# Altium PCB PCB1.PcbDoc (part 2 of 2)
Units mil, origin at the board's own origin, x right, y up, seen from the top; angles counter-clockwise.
Board outline 3935 x 3935 mil, 2 copper layers (Top Layer, Bottom Layer); 151 components, 133 nets, 573 pads, 224 vias.
Unrouted connection lines stored in the file: 1.
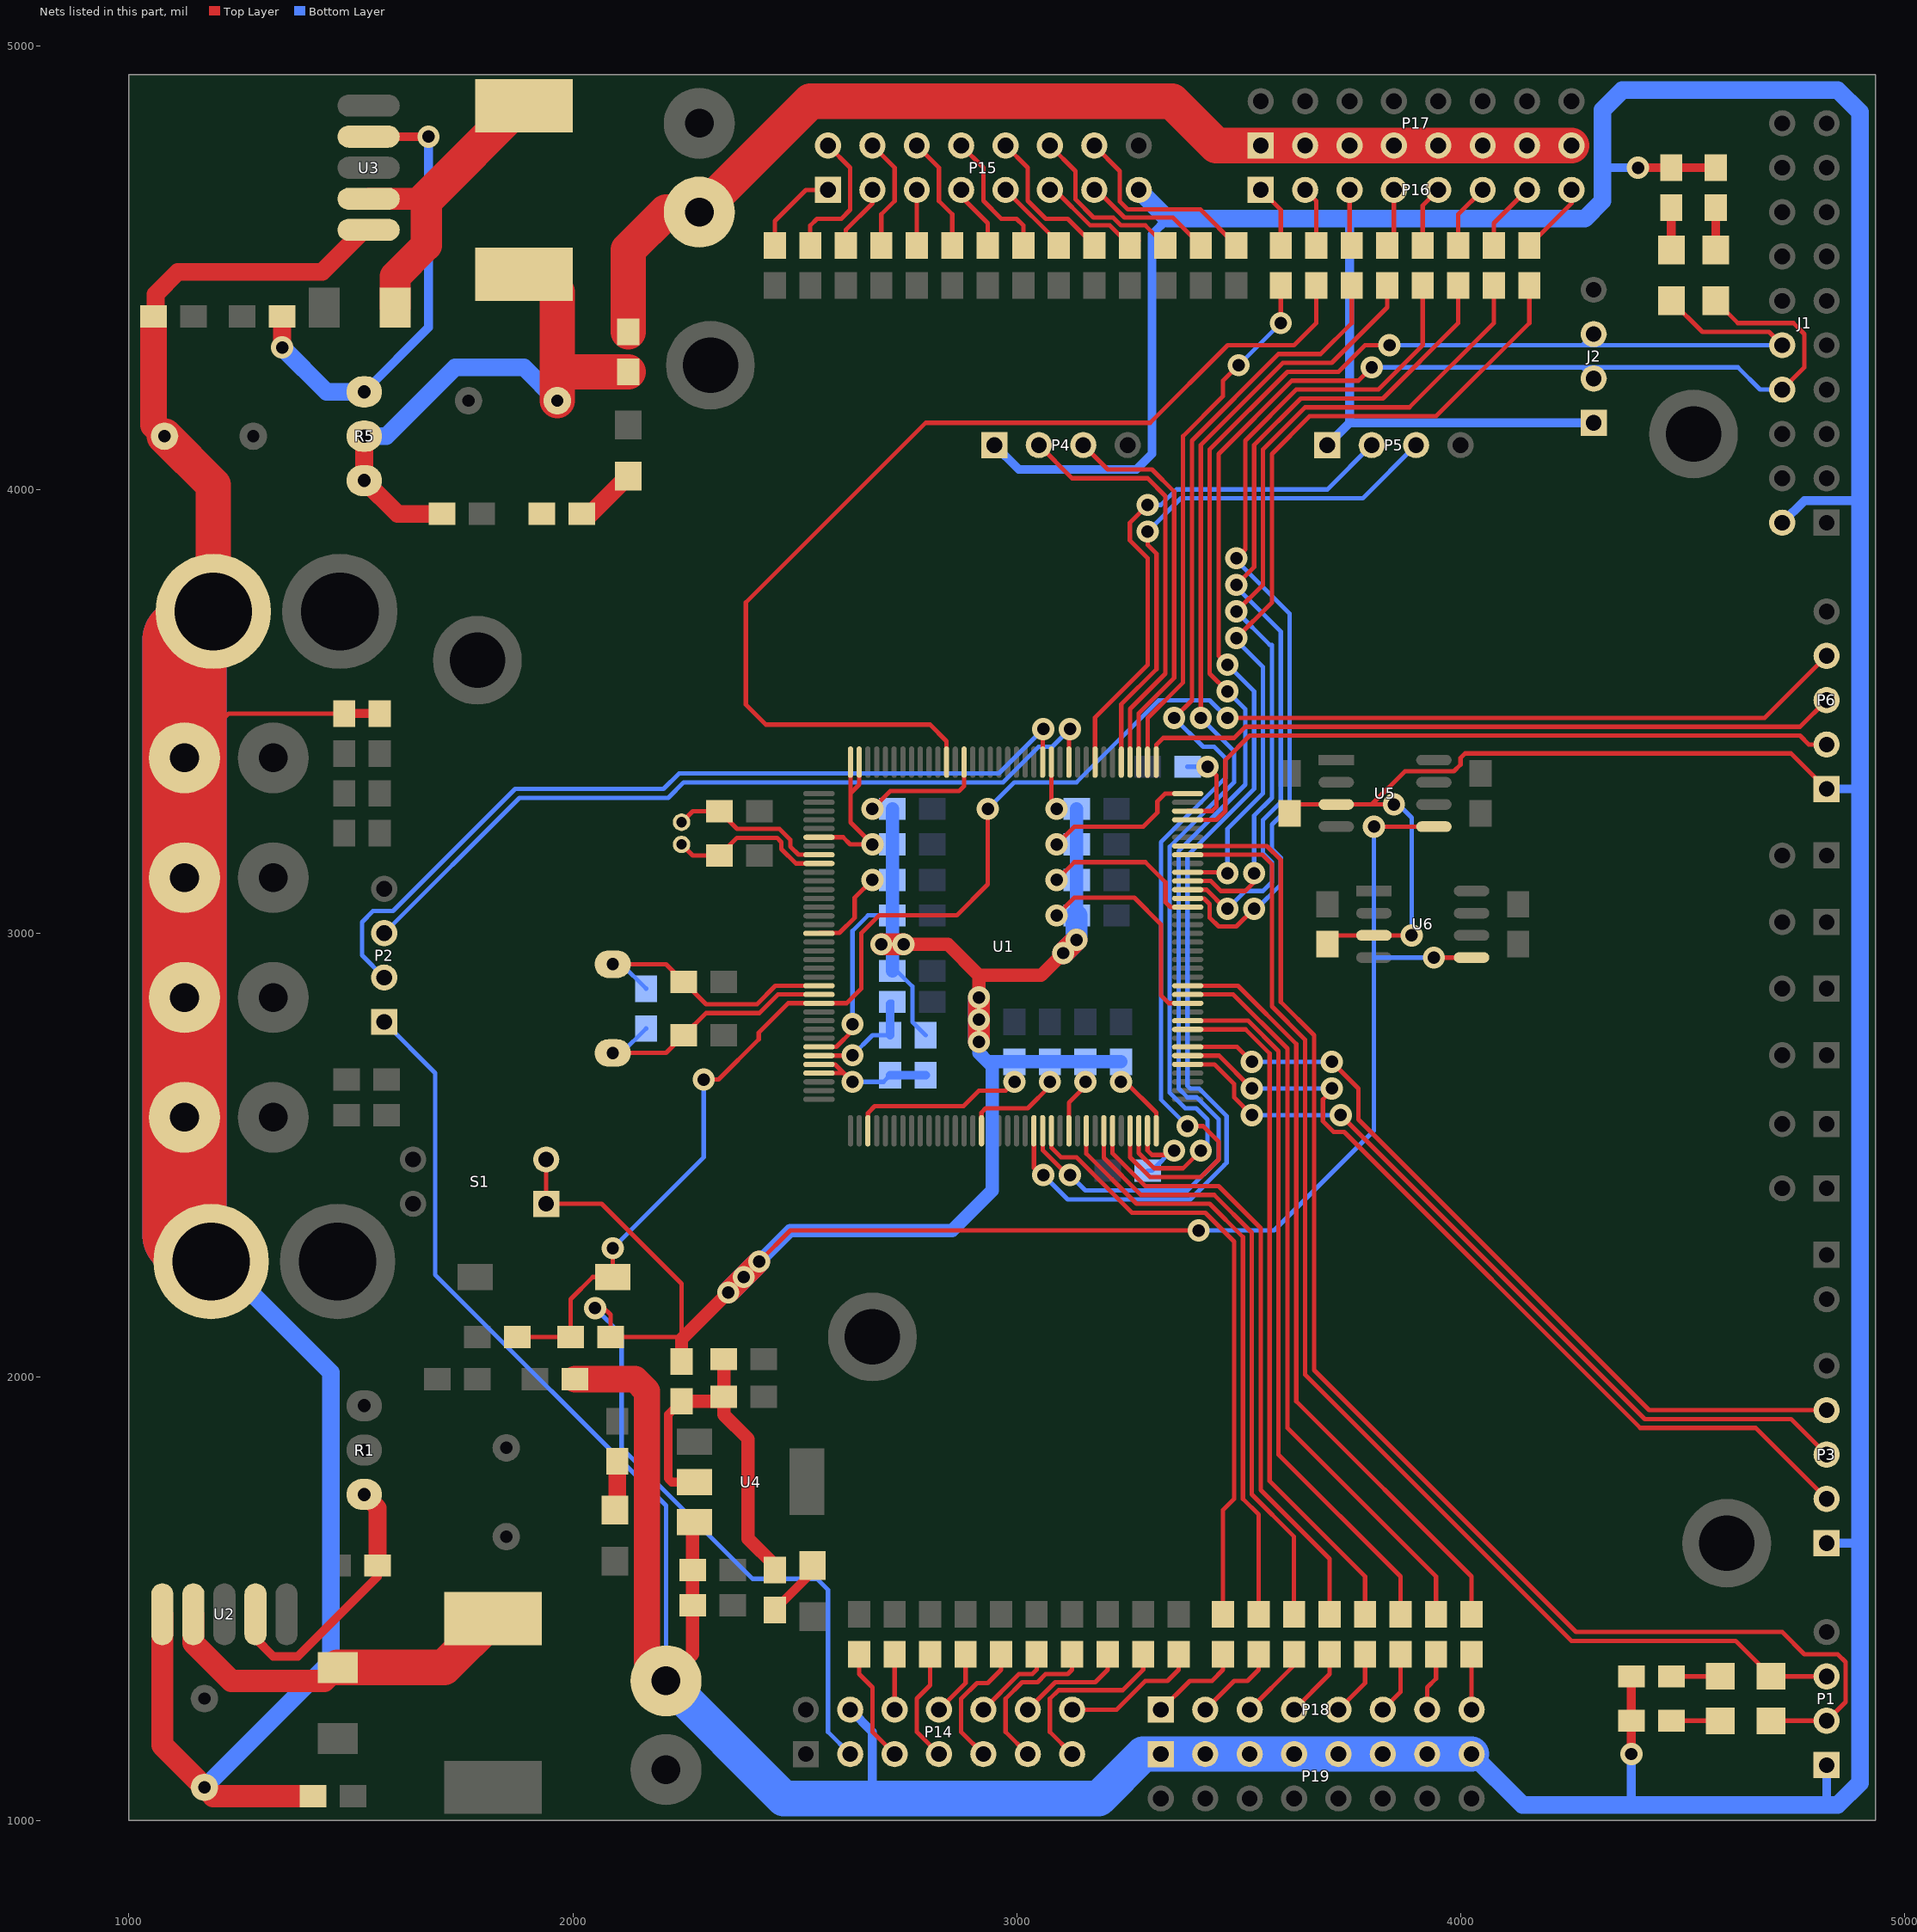
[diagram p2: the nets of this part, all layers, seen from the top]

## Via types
v1: diameter 50, hole 28, Top Layer to Bottom Layer, tented both sides, 126 vias
v2: diameter 30, hole 20, Top Layer to Bottom Layer, tented both sides, 98 vias

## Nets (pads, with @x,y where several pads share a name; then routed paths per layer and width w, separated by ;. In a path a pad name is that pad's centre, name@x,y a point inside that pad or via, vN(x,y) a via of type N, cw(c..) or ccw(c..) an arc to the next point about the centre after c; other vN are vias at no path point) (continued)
NetC7_1: C7.1 C8.1 L2.2 R5.2 R5.3 R7.1 R8.1 | length 1297.9
  Top Layer w40: R5.2@1530,4120 R5.3@1530,4020 1605,3945 C7.1@1705,3945
  Top Layer w80: L2.2@1925,4485 1965,4445 1965,4265 ; C8.1@1965,4200 1965,4265 ; R8.1@2125,4265 1965,4265
  Bottom Layer w40: R5.2@1530,4120 1580,4120 1735,4275 1890,4275 C8.1@1965,4200
NetC11_1: C11.1 C12.2 R9.1 R65.2 U4.2 | length 870.5
  Top Layer w10: C12.2@2330,1945 C12.2@2340,1955
  Top Layer w20: R9.1@2245,1945 2215,1915 2215,1771 2223,1763 U4.2@2274,1763 ; R65.2@2455,1565 R65.2@2455,1575
  Top Layer w30: R9.1@2245,1945 C12.2@2330,1945 ; C11.1@2340,2040 C12.2@2340,1955 2340,1915 2395,1860 2395,1635 R65.2@2455,1575
NetC19_1: C19.1 R20.2 U1.23 Y1.1 | length 616.9
  Top Layer w10: Y1.1@2090,2930 2210,2930 C19.1@2250,2890 2300,2840 2415,2840 2456.42,2881.42 U1.23@2554.65,2881.42
  Bottom Layer w10: Y1.1@2090,2930 2110,2930 R20.2@2165,2875
NetC20_1: C20.1 R20.1 U1.24 Y1.2 | length 617
  Top Layer w10: Y1.2@2090,2730 2210,2730 C20.1@2250,2770 2300,2820 2420.46,2820 2462.19,2861.73 U1.24@2554.65,2861.73
  Bottom Layer w10: Y1.2@2090,2730 2110,2730 R20.1@2165,2785
NetC21_2: C21.2 U1.106 | length 212
  Top Layer w10: U1.106@3385.35,3275.12 3440.12,3275.12 3450,3285 3450,3355 v1(3430,3375)
  Bottom Layer w10: C21.2@3385,3375 v1(3430,3375)
NetC22_2: C22.2 U1.71 | length 198.7
  Top Layer w10: U1.71@3294.8,2554.65 3294.8,2510.2 3305,2500 3345,2500 v1(3355,2510)
  Bottom Layer w10: C22.2@3295,2465 3305,2465 3355,2515 v1(3355,2510)
NetC23_2: C23.2 U1.8 Y2.2 | length 369.8
  Top Layer w10: Y2.2@2245,3250 2270,3275 C23.2@2330,3275 2370,3235 2465.46,3235 2490,3210.46 2490,3195 2508.31,3176.69 U1.8@2554.65,3176.69
NetC24_2: C24.2 U1.9 Y2.1 | length 369.6
  Top Layer w10: Y2.1@2245,3200 2270,3175 C24.2@2330,3175 2370,3215 2460,3215 2470,3205 2470,3189.54 2502.54,3157.01 U1.9@2554.65,3157.01
NetD1_2: D1.2 L1.1 U2.2 | length 833
  Top Layer w50: U2.2@1145,1465 1145,1400.41 1230.41,1315 1440,1315 D1.2@1470,1345
  Top Layer w80: D1.2@1470,1345 1710,1345 L1.1@1820,1455
NetD2_1: D2.1 R3.2 | length 112.1
  Top Layer w10: D2.1@2095,1700 D2.1@2100,1705
  Top Layer w40: D2.1@2100,1705 R3.2@2100,1810
NetD3_2: D3.2 L2.1 U3.2 | length 749.5
  Top Layer w50: U3.2@1540,4655 1670,4655
  Top Layer w70: D3.2@1600,4410 1600,4480 1670,4550 1670,4655
  Top Layer w80: 1670,4655 1882.5,4867.5 L2.1@1927.5,4867.5
NetD4_1: D4.1 R7.2 | length 140.2
  Top Layer w10: R7.2@2020,3945 R7.2@2040,3945
  Top Layer w40: R7.2@2040,3945 D4.1@2125,4030
NetD5_1: D5.1 R65.1 | length 135.2
  Top Layer w10: D5.1@2540,1560 D5.1@2540,1575
  Top Layer w20: R65.1@2455,1475 D5.1@2540,1560
NetD6_1: D6.1 R66.1 | length 110
  Top Layer w10: R66.1@4475,1225 D6.1@4585,1225
NetD7_1: D7.1 R67.1 | length 110
  Top Layer w10: R67.1@4475,1325 D7.1@4585,1325
NetD8_1: D8.1 R68.1 | length 95
  Top Layer w20: D8.1@4575,4540 R68.1@4575,4635
NetD9_1: D9.1 R69.1 | length 95
  Top Layer w20: D9.1@4475,4540 R69.1@4475,4635
NetP14_5: P14.5 R25.2 | length 258.1
  Top Layer w10: R25.2@2645,1375 2645,1330 2675,1300 2675,1200 P14.5@2725,1150
NetP14_6: P14.6 R26.1 | length 125
  Top Layer w10: P14.6@2725,1250 R26.1@2725,1375
NetP14_7: P14.7 R27.2 | length 258.1
  Top Layer w10: R27.2@2805,1375 2805,1305 2775,1275 2775,1200 P14.7@2825,1150
NetP14_8: P14.8 R28.1 | length 149.9
  Top Layer w10: P14.8@2825,1250 2885,1310 R28.1@2885,1375
NetP14_9: P14.9 R29.2 | length 297.4
  Top Layer w10: P14.9@2925,1150 2875,1200 2875,1274.54 2910.46,1310 2935,1310 2965,1340 R29.2@2965,1375
NetP14_10: P14.10 R30.1 | length 192.3
  Top Layer w10: P14.10@2925,1250 3005,1330 3035,1330 3045,1340 R30.1@3045,1375
NetP14_11: P14.11 R31.2 | length 357.4
  Top Layer w10: P14.11@3025,1150 2975,1200 2975,1274.54 3012.46,1312 3047,1312 3065,1330 3115,1330 3125,1340 R31.2@3125,1375
NetP14_12: P14.12 R32.1 | length 252.3
  Top Layer w10: P14.12@3025,1250 3087,1312 3177,1312 3205,1340 R32.1@3205,1375
NetP14_13: P14.13 R33.2 | length 417.4
  Top Layer w10: P14.13@3125,1150 3075,1200 3075,1274.54 3094.46,1294 3239,1294 3285,1340 R33.2@3285,1375
NetP14_14: P14.14 R34.1 | length 312.3
  Top Layer w10: P14.14@3125,1250 3225,1250 3290,1315 3340,1315 3365,1340 R34.1@3365,1375
NetP15_1: P15.1 R35.2 | length 208.1
  Top Layer w10: R35.2@2465,4550 2455,4560 2455,4605 2525,4675 P15.1@2575,4675
NetP15_2: P15.2 R36.1 | length 315.2
  Top Layer w10: R36.1@2535,4550 2535,4595 2550,4610 2605,4610 2625,4630 2625,4725 P15.2@2575,4775
NetP15_3: P15.3 R37.2 | length 149.9
  Top Layer w10: R37.2@2615,4550 2615,4585 2675,4645 P15.3@2675,4675
NetP15_4: P15.4 R38.1 | length 258.1
  Top Layer w10: P15.4@2675,4775 2725,4725 2725,4650 2695,4620 R38.1@2695,4550
NetP15_5: P15.5 R39.2 | length 125
  Top Layer w10: R39.2@2775,4550 P15.5@2775,4675
NetP15_6: P15.6 R40.1 | length 258.1
  Top Layer w10: P15.6@2775,4775 2825,4725 2825,4650 2855,4620 R40.1@2855,4550
NetP15_7: P15.7 R41.2 | length 149.9
  Top Layer w10: P15.7@2875,4675 2875,4660 2935,4600 R41.2@2935,4550
NetP15_8: P15.8 R42.1 | length 303.2
  Top Layer w10: P15.8@2875,4775 2925,4725 2925,4650.46 2965.46,4610 3000,4610 3015,4595 R42.1@3015,4550
NetP15_9: P15.9 R43.2 | length 174.7
  Top Layer w10: P15.9@2975,4675 3095,4555 R43.2@3095,4550
NetP15_10: P15.10 R44.1 | length 336.9
  Top Layer w10: P15.10@2975,4775 3025,4725 3025,4650.46 3065.46,4610 3115,4610 R44.1@3175,4550
NetP15_11: P15.11 R45.2 | length 245.9
  Top Layer w10: P15.11@3075,4675 3085.91,4675 3165.91,4595 3210,4595 R45.2@3255,4550 ; R45.2@3265,4570 R45.2@3275,4560
NetP15_12: P15.12 R46.1 | length 390.5
  Top Layer w10: P15.12@3075,4775 3132.47,4717.53 3132.47,4653.9 3173.37,4613 3217.46,4613 3235.46,4595 3290,4595 R46.1@3335,4550
NetP15_13: P15.13 R47.2 | length 291.8
  Top Layer w10: P15.13@3175,4675 3180.91,4675 3242.91,4613 3352,4613 R47.2@3415,4550
NetP15_14: P15.14 R48.1 | length 453.4
  Top Layer w10: P15.14@3175,4775 3232.47,4717.53 3232.47,4648.9 3250.37,4631 3414,4631 R48.1@3495,4550
NetP16_1: P16.1 R49.2 | length 143.6
  Top Layer w10: P16.1@3550,4675 3595,4630 R49.2@3595,4550
NetP16_2: P16.2 R50.2 | length 135.4
  Top Layer w10: P16.2@3650,4675 3675,4650 R50.2@3675,4550
NetP16_3: P16.3 R51.2 | length 127.1
  Top Layer w10: P16.3@3750,4675 3750,4555 R51.2@3755,4550
NetP16_4: P16.4 R52.2 | length 131.2
  Top Layer w10: R52.2@3835,4550 3850,4565 P16.4@3850,4675
NetP16_5: P16.5 R53.2 | length 139.5
  Top Layer w10: R53.2@3915,4550 3915,4640 P16.5@3950,4675
NetP16_6: P16.6 R54.2 | length 147.8
  Top Layer w10: R54.2@3995,4550 3995,4620 P16.6@4050,4675
NetP16_7: P16.7 R55.2 | length 156.1
  Top Layer w10: R55.2@4075,4550 4075,4600 P16.7@4150,4675
NetP16_8: P16.8 R56.2 | length 164.4
  Top Layer w10: R56.2@4155,4550 4250,4645 P16.8@4250,4675
NetP18_1: P18.1 R57.2 | length 212.3
  Top Layer w10: P18.1@3325,1250 3390,1315 3440,1315 3465,1340 R57.2@3465,1375
NetP18_2: P18.2 R58.2 | length 192.3
  Top Layer w10: P18.2@3425,1250 3490,1315 3520,1315 3545,1340 R58.2@3545,1375
NetP18_3: P18.3 R59.2 | length 151.4
  Top Layer w10: P18.3@3525,1250 R59.2@3625,1350 ; R59.2@3625,1365 R59.2@3625,1375
NetP18_4: P18.4 R60.2 | length 158.1
  Top Layer w10: P18.4@3625,1250 3705,1330 R60.2@3705,1375
NetP18_5: P18.5 R61.2 | length 149.9
  Top Layer w10: P18.5@3725,1250 3785,1310 R61.2@3785,1375
NetP18_6: P18.6 R62.2 | length 141.6
  Top Layer w10: P18.6@3825,1250 3865,1290 R62.2@3865,1375
NetP18_7: P18.7 R63.2 | length 133.3
  Top Layer w10: P18.7@3925,1250 3925,1300 3945,1320 R63.2@3945,1375
NetP18_8: P18.8 R64.2 | length 110
  Top Layer w10: P18.8@4025,1250 R64.2@4025,1360
NetR1_1: R1.1 R2.2 U2.4 | length 618.6
  Top Layer w10: U2.4@1285,1410 U2.4@1285,1465
  Top Layer w20: U2.4@1285,1410 1325,1370 1380,1370 1560,1550 R2.2@1560,1575
  Top Layer w40: R1.1@1530,1735 1560,1705 R2.2@1560,1575
NetR5_1: R5.1 R6.2 U3.4 | length 1051.5
  Top Layer w20: U3.4@1540,4795 v1(1675,4795)
  Top Layer w40: v1(1345,4320) R6.2@1345,4375
  Bottom Layer w20: R5.1@1530,4220 1675,4365 v1(1675,4795)
  Bottom Layer w40: v1(1345,4320) 1445,4220 R5.1@1530,4220
RST: C15.1 P6.4 R12.1 S2.2 U1.25 | length 3990.9
  Top Layer w10: C15.1@1875,2090 R12.1@1995,2090 1995,2175 2045,2225 S2.2@2090,2225 v1(2090,2290) ; v1(2295,2670) 2328.18,2670 2419,2760.82 2419,2775.82 2485.22,2842.05 U1.25@2554.65,2842.05 2617.05,2842.05 2650,2875 2650,3000 2690,3040 2865,3040 2935,3110 v1(2935,3280) ; v1(3475,3485) 4685,3485 P6.4@4825,3625
  Bottom Layer w10: v1(2090,2290) 2295,2495 v1(2295,2670) ; v1(2935,3280) 2995,3340 3135,3340 3320,3525 3435,3525 v1(3475,3485)
SWCLK: P6.3 U1.109 | length 1591.3
  Top Layer w10: U1.109@3314.49,3385.35 3314.49,3424.49 3330,3440 3490,3440 3515,3465 4765,3465 P6.3@4825,3525
SWDIO: P6.2 U1.105 | length 1593.8
  Top Layer w10: U1.105@3385.35,3255.43 3450.43,3255.43 3470,3275 3470,3390 3525,3445 4765,3445 4785,3425 P6.2@4825,3425
TIM1_CH1: R57.1 U1.60 | length 1387.7
  Top Layer w10: U1.60@3078.27,2554.65 3078.27,2516.73 3100,2495 3135,2495 3260,2370 3425,2370 3490,2305 3490,1725 3465,1700 R57.1@3465,1465
TIM1_CH2: R58.1 U1.64 | length 1347
  Top Layer w10: U1.64@3157.01,2554.65 3157.01,2502.99 3270,2390 3435,2390 3510,2315 3510,1725 3545,1690 R58.1@3545,1465
TIM1_CH3: R59.1 U1.66 | length 1363.8
  Top Layer w10: U1.66@3196.38,2554.65 3196.38,2493.62 3280,2410 3445,2410 3530,2325 3530,1735 3625,1640 R59.1@3625,1465
TIM1_CH4: R60.1 U1.67 | length 1388.8
  Top Layer w10: U1.67@3216.06,2554.65 3216.06,2503.94 3290,2430 3455,2430 3550,2335 3550,1745 3705,1590 R60.1@3705,1465
TIM2_CH1: R49.1 U1.110 | length 1199
  Top Layer w10: U1.110@3294.8,3385.35 3295,3385.55 3295,3485 3375,3565 3375,4120 3465,4210 3465,4245 v1(3500,4280) ; v1(3595,4375) R49.1@3595,4460
  Bottom Layer w10: v1(3500,4280) v1(3595,4375)
TIM2_CH2: R50.1 U1.133 | length 2394.6
  Top Layer w10: U1.133@2842.05,3385.35 2842.05,3432.95 2805,3470 2435,3470 2390,3515 2390,3745 2795,4150 3300.46,4150 3475.46,4325 3625,4325 3675,4375 R50.1@3675,4460
TIM2_CH3: R51.1 U1.69 | length 2682.4
  Top Layer w10: U1.69@3255.43,2554.65 3255.43,2495.02 3300.46,2450 3415,2450 3455,2490 3455,2530 3420,2565 v1(3385,2565) ; v1(3355,3485) 3395,3525 3395,4110 3590,4305 3685,4305 3755,4375 R51.1@3755,4460
  Bottom Layer w10: v1(3355,3485) 3420,3420 3445,3420 3470,3395 3470,3350 3325,3205 3325,2625 v1(3385,2565)
TIM2_CH4: R52.1 U1.70 | length 2579.5
  Top Layer w10: U1.70@3275.12,2554.65 3275.12,2504.43 3309.54,2470 3375,2470 v1(3415,2510) ; v1(3415,3485) 3415,4100 3600,4285 3710,4285 3835,4410 R52.1@3835,4460
  Bottom Layer w10: v1(3415,2510) 3420,2510 3430,2500 3430,2580 3405,2605 3380,2605 3345,2640 3345,3195 3490,3340 3490,3410 v1(3415,3485)
TIM3_CH1: R53.1 U1.96 | length 2000.1
  Top Layer w10: U1.96@3385.35,3078.27 3422.08,3078.27 3435,3065.35 3435,3035 3455,3015 3495,3015 v1(3535,3055) ; v1(3495,3845) 3515,3865 3515,4110 3630,4225 3815,4225 3915,4325 R53.1@3915,4460
  Bottom Layer w10: v1(3495,3845) 3495,3840 3615,3720 3615,3285 3575,3245 3575,3190 3595,3170 3595,3109.54 3540.46,3055 v1(3535,3055)
TIM3_CH2: R54.1 U1.97 | length 1959
  Top Layer w10: U1.97@3385.35,3097.95 3427.85,3097.95 3470.8,3055 v1(3475,3055) ; v1(3495,3785) 3535,3825 3535,4100 3640,4205 3825,4205 3995,4375 R54.1@3995,4460
  Bottom Layer w10: v1(3475,3055) 3515,3095 3555,3095 3575,3115 3575,3160 3555,3180 3555,3255 3595,3295 3595,3680 3495,3780 v1(3495,3785)
TIM3_CH3: R55.1 U1.98 | length 1942.8
  Top Layer w10: U1.98@3385.35,3117.64 3437.36,3117.64 3460,3095 3515,3095 3535,3115 v1(3535,3135) ; v1(3495,3725) 3555,3785 3555,4090 3650,4185 3885,4185 4075,4375 R55.1@4075,4460
  Bottom Layer w10: v1(3495,3725) 3570,3650 3575,3650 3575,3305 3535,3265 v1(3535,3135)
TIM3_CH4: R56.1 U1.99 | length 1908
  Top Layer w10: U1.99@3385.35,3137.32 v1@3470,3137.32 ; v1(3495,3665) 3575,3745 3575,4080 3660,4165 3945,4165 4155,4375 R56.1@4155,4460
  Bottom Layer w10: v1(3475,3135) 3475,3235 3555,3315 3555,3600 3495,3660 v1(3495,3665)
TIM4_CH1: R61.1 U1.81 | length 1559.9
  Top Layer w10: U1.81@3385.35,2782.99 3515.75,2782.99 3570,2728.74 3570,1765 3785,1550 R61.1@3785,1465
TIM4_CH2: R62.1 U1.82 | length 1616.1
  Top Layer w10: U1.82@3385.35,2802.68 3521.52,2802.68 3590,2734.2 3590,1825 3865,1550 R62.1@3865,1465
TIM4_CH3: R63.1 U1.85 | length 1688.8
  Top Layer w10: U1.85@3385.35,2861.73 3488.27,2861.73 3610,2740 3610,1885 3945,1550 R63.1@3945,1465
TIM4_CH4: R64.1 U1.86 | length 1747.7
  Top Layer w10: U1.86@3385.35,2881.42 3498.58,2881.42 3630,2750 3630,1945 4025,1550 R64.1@4025,1465
UART4_RX: P4.2 U1.112 | length 965.2
  Top Layer w10: P4.2@3050,4100 3125,4025 3295,4025 3335,3985 3335,3585 3255.43,3505.43 U1.112@3255.43,3385.35
UART4_TX: P4.3 U1.111 | length 891.2
  Top Layer w10: P4.3@3150,4100 3205,4045 3305,4045 3355,3995 3355,3575 3275.12,3495.12 U1.111@3275.12,3385.35
UART5_RX: P5.2 U1.116 | length 1222.7
  Top Layer w10: U1.116@3176.69,3385.35 3176.69,3486.24 3295,3604.54 3295,3845 3255,3885 3255,3925 v1(3295,3965)
  Bottom Layer w10: v1(3295,3965) 3325,3965 3360,4000 3700,4000 P5.2@3800,4100
UART5_TX: P5.3 U1.113 | length 1246.5
  Top Layer w10: U1.113@3235.75,3385.35 3235.75,3515.75 3315,3595 3315,3855 3295,3875 v1(3295,3905)
  Bottom Layer w10: v1(3295,3905) 3370,3980 3780,3980 P5.3@3900,4100
UART7_RX: D8.2 J1.8 J2.2 U1.58 | length 4106.1
  Top Layer w10: U1.58@3038.9,2554.65 3038.9,2471.1 3055,2455 v1(3060,2455) ; v1(3475,3605) 3455,3625 3455,4080 3620,4245 3770,4245 v1(3800,4275) ; D8.2@4575,4425 4625,4375 4750,4375 4775,4350 4775,4275 J1.8@4725,4225
  Bottom Layer w10: v1(3060,2455) 3115,2400 3391.25,2400 3467,2475.75 3467,2476.54 3473,2482.54 3473,2587.91 3410.91,2650 3391.25,2650 3385,2656.25 3385,3175 3535,3325 3535,3545 v1(3475,3605) ; v1(3800,4275) 4275,4275 ; J2.2@4300,4250 4275,4275 ; J1.8@4725,4225 4675,4225 4625,4275 4275,4275
UART7_TX: D9.2 J1.10 J2.3 U1.59 | length 3980.4
  Top Layer w10: U1.59@3058.58,2554.65 3058.58,2510.96 3114.54,2455 v1(3120,2455) ; v1(3475,3545) 3435,3585 3435,4090 3610,4265 3725,4265 3785,4325 v1(3840,4325) ; D9.2@4460,4425 D9.2@4475,4425 4545,4355 4695,4355 J1.10@4725,4325
  Bottom Layer w10: v1(3120,2455) 3155,2420 3385,2420 3455,2490 3455,2580.46 3405.46,2630 3385,2630 3365,2650 3365,3185 3515,3335 3515,3505 v1(3475,3545) ; v1(3840,4325) 4275,4325 ; J2.3@4300,4350 4275,4325 ; J1.10@4725,4325 4275,4325
USART1_RX: D6.2 P1.2 U1.102 | length 3148.7
  Top Layer w10: U1.102@3385.35,3196.38 3563.62,3196.38 3595,3165 3595,2845 3670,2770 3670,2015 4260,1425 4725,1425 4775,1375 4850,1375 4867.53,1357.47 4867.53,1267.53 P1.2@4825,1225 D6.2@4700,1225
USART1_TX: D7.2 P1.3 U1.101 | length 2836.4
  Top Layer w10: U1.101@3385.35,3176.69 3553.31,3176.69 3575,3155 3575,2835 3650,2760 3650,2005 4250,1405 4620,1405 D7.2@4700,1325 P1.3@4825,1325
USART2_RX: P2.2 U1.122 | length 1935.5
  Top Layer w10: U1.122@3058.58,3385.35 v1@3058.58,3460
  Bottom Layer w10: P2.2@1575,2900 1525,2950 1525,3025 1550,3050 1595,3050 1870,3325 2204.54,3325 2239.54,3360 2960,3360 v1(3060,3460)
USART2_TX: P2.3 U1.119 | length 1802.8
  Top Layer w10: U1.119@3117.64,3385.35 v1@3117.64,3452.64
  Bottom Layer w10: P2.3@1575,3000 1880,3305 2215,3305 2250,3340 2969.54,3340 3049.54,3420 3080,3420 v1(3120,3460)
USART3_CK: P3.4 U1.79 | length 1819.7
  Top Layer w10: U1.79@3385.35,2743.62 3496.38,2743.62 v1(3530,2710) ; v1(3710,2710) 3770,2650 3770,2580 4425,1925 P3.4@4825,1925
  Bottom Layer w10: v1(3530,2710) v1(3710,2710)
USART3_RX: P3.2 U1.78 | length 1924.9
  Top Layer w10: U1.78@3385.35,2723.94 3456.06,2723.94 v1(3530,2650) ; v1(3710,2650) 3710,2645 3690,2625 3690,2576.26 3714.26,2552 3738,2552 4405,1885 4665,1885 P3.2@4825,1725
  Bottom Layer w10: v1(3530,2650) v1(3710,2650)
USART3_TX: P3.3 U1.77 | length 1821.4
  Top Layer w10: U1.77@3385.35,2704.25 3445.75,2704.25 3490,2660 3490,2630 v1(3530,2590) ; v1(3730,2590) 4415,1905 4745,1905 P3.3@4825,1825
  Bottom Layer w10: v1(3530,2590) v1(3730,2590)
VCC_5V: C9.1 C10.2 C25.1 C26.1 J1.2 J2.1 P1.1 P2.1 P3.1 P4.1 P5.1 P6.1 P14.4 P15.15 P19.1 P19.3 P19.5 P19.7 P19.9 P19.11 P19.13 P19.15 R4.2 R66.2 R67.2 R68.2 R69.2 U4.3 U5.3 U6.3 X8.1 | length 16655.8
  Top Layer w10: U4.3@2270,1668.45 U4.3@2274,1672.45 ; C25.1@3615,3270 3635,3290 U5.3@3720,3290 3800,3290 ; C26.1@3700,2975 3720,2995 U6.3@3805,2995 v1(3890,2995) ; v1(3850,3290) 3800,3290 ; P6.1@4825,3325 4824.54,3325 4744.54,3405 4010,3405 4000,3395 4000,3380 3985,3365 3875,3365 3800,3290
  Top Layer w20: v1(4385,1150) R66.2@4385,1225 R67.2@4385,1325 ; v1(4400,4725) R69.2@4475,4725 R68.2@4575,4725
  Top Layer w30: X8.1@2210,1315 2270,1375 C10.2@2270,1485 C9.1@2270,1565 U4.3@2270,1668.45
  Top Layer w60: R4.2@2005,1995 2140,1995 2167,1968 2167,1358 X8.1@2210,1315
  Bottom Layer w10: P2.1@1575,2800 1690,2685 1690,2230 2210,1710 X8.1@2210,1315 ; v1(3850,3290) 3860,3290 3890,3260 v1(3890,2995)
  Bottom Layer w20: P14.4@2625,1250 2675,1200 2675,1050 ; P4.1@2950,4100 3005,4045 3270,4045 3305,4080 3305,4575 3340,4610 ; P5.1@3700,4100 3750,4150 ; 3750,4610 3750,4150 ; J2.1@4300,4150 3750,4150 ; 4320,4725 v1(4400,4725) ; 4385,1035 v1(4385,1150) ; J1.2@4725,3925 4775,3975 4900,3975 ; 4825,1035 P1.1@4825,1125 ; P3.1@4825,1625 4900,1625 ; P6.1@4825,3325 4900,3325
  Bottom Layer w40: P15.15@3275,4675 3340,4610 3750,4610 4280,4610 4320,4650 4320,4725 4320,4855 4365,4900 4850,4900 4900,4850 4900,3975 4900,3325 4900,1625 4900,1085 4850,1035 4825,1035 4385,1035 4140,1035 P19.15@4025,1150
  Bottom Layer w80: X8.1@2210,1315 2475,1050 2675,1050 3185,1050 3285,1150 P19.1@3325,1150 P19.3@3425,1150 P19.5@3525,1150 P19.7@3625,1150 P19.9@3725,1150 P19.11@3825,1150 P19.13@3925,1150 P19.15@4025,1150
VCC_24V: C1.1 C2.2 C5.1 C6.2 C17.2 R18.2 U2.1 U3.1 X1.1 X2.1 X3.1 X4.1 X5.1 X6.1 | length 6840.3
  Top Layer w10: X6.1@1125,3395 1225,3495 R18.2@1485,3495
  Top Layer w20: R18.2@1485,3495 C17.2@1565,3495 C17.2@1575,3495
  Top Layer w40: C6.2@1060,4385 1060,4440 1110,4490 1435,4490 U3.1@1530,4585
  Top Layer w50: U2.1@1075,1465 1075,1170 C1.1@1170,1075 1190,1055 C2.2@1415,1055
  Top Layer w60: C6.2@1055,4375 1055,4145 C5.1@1080,4120
  Top Layer w80: C5.1@1080,4120 1190,4010 X2.1@1190,3725
  Top Layer w190: X1.1@1185,2260 1125,2320 X3.1@1125,2585 X4.1@1125,2855 X5.1@1125,3125 X6.1@1125,3395 1125,3660 X2.1@1190,3725
  Bottom Layer w10: X2.1@1125,3660 X2.1@1190,3725
  Bottom Layer w40: C1.1@1170,1075 1455,1360 1455,2010 1205,2260 X1.1@1185,2260
  Bottom Layer w190: X1.1@1125,2320 X3.1@1125,2585 X4.1@1125,2855 X5.1@1125,3125 X6.1@1125,3395 X2.1@1125,3660
VCC_ADJ: P17.1 P17.3 P17.5 P17.7 P17.9 P17.11 P17.13 P17.15 R8.2 X7.1 | length 2490.2
  Top Layer w80: R8.2@2125,4355 2125,4540 2210,4625 X7.1@2285,4625 2535,4875 3350,4875 3450,4775 P17.1@3550,4775 P17.3@3650,4775 P17.5@3750,4775 P17.7@3850,4775 P17.9@3950,4775 P17.11@4050,4775 P17.13@4150,4775 P17.15@4250,4775
VDD_3V3: C14.2 C27.2 C28.2 C29.2 C30.2 C31.2 C32.2 C33.2 C34.2 C35.2 C36.2 C37.2 C38.2 P14.3 R9.2 R10.2 R12.2 S1.1 S1.2 U1.6 U1.17 U1.30 U1.39 U1.52 U1.62 U1.72 U1.84 U1.95 U1.108 U1.121 U1.131 U1.143 U1.144 U5.5 U6.5 | length 11549
  Top Layer w10: S1.2@1940,2490 S1.1@1940,2390 2065,2390 2245,2210 2245,2095 ; v1(2050,2155) 2070,2155 2085,2140 R12.2@2085,2095 ; R12.2@2085,2090 2245,2090 2245,2085 ; v1(2420,2260) 2490,2330 v1(3410,2330) ; U1.30@2554.65,2743.62 2593.62,2743.62 2630,2780 v1(2630,2795) ; U1.17@2554.65,2999.53 2555.43,3000.31 2600.76,3000.31 2635,3034.54 2635,3080 v1(2675,3120) ; U1.6@2554.65,3216.06 2608.94,3216.06 2625,3200 v1(2675,3200) 2625.51,3249.49 2625.51,3315 ; U1.144@2625.51,3385.35 2625.51,3315 ; U1.143@2645.2,3385.35 2645.2,3334.69 2625.51,3315 ; U1.39@2664.88,2554.65 2664.88,2594.88 2680,2610 2880,2610 2915,2645 2975,2645 v1(2995,2665) ; v1(2675,3280) 2715,3320 2870,3320 2881.42,3331.42 U1.131@2881.42,3385.35 ; U1.52@2920.79,2554.65 2920.79,2595.79 2930,2605 3025,2605 3075,2655 v1(3075,2665) ; U1.121@3078.27,3385.35 3078.27,3291.73 v1(3090,3280) ; v1(3090,3040) 3130,3080 3265,3080 3325,3020 3325,2860 3342.95,2842.05 U1.84@3385.35,2842.05 ; v1(3090,3120) 3130,3160 3290,3160 3335.55,3114.45 3335.55,3069.45 3346.42,3058.58 U1.95@3385.35,3058.58 ; v1(3090,3200) 3130,3240 3285,3240 3317,3272 3317,3297 3334.49,3314.49 U1.108@3385.35,3314.49 ; U1.62@3117.64,2554.65 3117.64,2617.64 3155,2655 v1(3155,2665) ; v1(3235,2665) 3245,2665 3314.49,2595.51 U1.72@3314.49,2554.65 ; v1(3805,3240) U5.5@3940,3240 ; v1(3940,2945) U6.5@4025,2945
  Top Layer w30: R9.2@2245,2035 2245,2085 v1(2350,2190) ; v1(2745,2975) 2845,2975 2915,2905 3055,2905 v1(3105,2955) ; v1(2915,2855) 2915,2895
  Top Layer w50: v1(2350,2190) v1(2385,2225) v1(2420,2260) ; v1(2695,2975) v1(2745,2975) ; v1(2915,2755) v1(2915,2805) v1(2915,2855) ; v1(3105,2955) v1(3135,2985)
  Bottom Layer w10: v1(2050,2155) 2110,2095 2110,1840 2405,1545 2550,1545 2575,1520 2575,1200 P14.3@2625,1150 ; v1(2630,2795) 2630,3005 2665,3040 C30.2@2720,3040 ; C14.2@2720,2915 2730,2915 2765,2880 2765,2800 R10.2@2795,2770 ; v1(3410,2330) 3580,2330 3805,2555 3805,2945 ; v1(3805,3240) 3805,2945 ; v1(3940,2945) 3805,2945
  Bottom Layer w30: v1(2420,2260) 2490,2330 2855,2330 2945,2420 2945,2700 2935,2710 ; C14.2@2720,2915 C30.2@2720,3040 C29.2@2720,3120 C28.2@2720,3200 C27.2@2720,3280 ; v1(2915,2755) 2915,2730 2935,2710 ; C34.2@3135,3040 C33.2@3135,3120 C32.2@3135,3200 C31.2@3135,3280 ; C38.2@3235,2710 C37.2@3155,2710 C36.2@3075,2710 C35.2@2995,2710 2935,2710
  Bottom Layer w50: v1(2350,2190) v1(2385,2225) v1(2420,2260) ; v1(2915,2755) v1(2915,2805) v1(2915,2855) ; v1(3105,2955) v1(3135,2985) C34.2@3135,3040
VDDA: C13.2 R10.1 U1.32 U1.33 | length 318.6
  Top Layer w10: U1.33@2554.65,2684.57 2610.43,2684.57 ; U1.32@2554.65,2704.25 2590.75,2704.25 2610.43,2684.57 ; v1(2630,2665) 2610.43,2684.57
  Bottom Layer w10: v1(2630,2665) 2700,2665 C13.2@2715,2680
  Bottom Layer w20: C13.2@2715,2680 R10.1@2795,2680
VSSA: C13.1 R11.1 U1.31 | length 256.5
  Top Layer w10: U1.31@2554.65,2723.94 2628.94,2723.94 v1(2630,2725)
  Bottom Layer w10: v1(2630,2725) 2675,2770 C13.1@2715,2770 ; R11.1@2715,2840 R11.1@2720,2845
  Bottom Layer w20: C13.1@2715,2770 R11.1@2715,2840
pads on no net: J1.1 J1.3 J1.4 J1.5 J1.7 J1.9 J1.11 J1.12 J1.13 J1.14 J1.15 J1.16 J1.17 J1.18 J1.19 J1.20 U1.1 U1.2 U1.3 U1.4 U1.5 U1.7 U1.10 U1.11 U1.12 U1.49 U1.50 U1.53 U1.54 U1.55 U1.56 U1.57 U1.63 U1.65 U1.68 U1.75 U1.76 U1.80 U1.87 U1.88 U1.89 U1.90 U1.91 U1.92 U1.93 U1.100 U1.114 U1.115 U1.117 U1.118 U1.123 U1.124 U1.125 U1.126 U1.127 U1.128 U1.129 U1.132 U1.134 U1.135 U1.136 U1.137 U1.139 U1.140 U1.141 U1.142 U4.4
copper on no net: | length 124.2
  Top Layer w50: 1162.5,1612.5 1215,1560
  Bottom Layer w10: 1210,4545 1260,4545
  other v2: 1065,1645 1115,1645 1165,1645 1215,1645 1265,1645 1315,1645 1365,1645 1065,1695 1115,1695 1165,1695 1215,1695 1265,1695 1315,1695 1365,1695 1065,1745 1115,1745 1165,1745 1215,1745 1265,1745 1315,1745 1365,1745 1065,1795 1115,1795 1165,1795 1215,1795 1265,1795 1315,1795 1365,1795 1065,1845 1115,1845 1165,1845 1215,1845 1265,1845 1315,1845 1365,1845 1065,1895 1115,1895 1165,1895 1215,1895 1265,1895 1315,1895 1365,1895 1065,1945 1115,1945 1165,1945 1215,1945 1265,1945 1315,1945 1365,1945 1060,4575 1110,4575 1160,4575 1210,4575 1260,4575 1310,4575 1360,4575 1060,4625 1110,4625 1160,4625 1210,4625 1260,4625 1310,4625 1360,4625 1060,4675 1110,4675 1160,4675 1210,4675 1260,4675 1310,4675 1360,4675 1060,4725 1110,4725 1160,4725 1210,4725 1260,4725 1310,4725 1360,4725 1060,4775 1110,4775 1160,4775 1210,4775 1260,4775 1310,4775 1360,4775 1060,4825 1110,4825 1160,4825 1210,4825 1260,4825 1310,4825 1360,4825 1060,4875 1110,4875 1160,4875 1210,4875 1260,4875 1310,4875 1360,4875

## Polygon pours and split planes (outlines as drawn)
GND on Bottom Layer "NONET_L01_P-001" (solid, remove dead copper, pour order 58): 4935,4935 4935,1010 4935,1000 1000,1000 1000,4935 4935,4935 3340,3340 3340,2600 2600,2600 2600,3340 3340,3340
GND on Top Layer "NONET_L01_P-001" (solid, remove dead copper, pour order 60): 4935,4935 4935,1000 1000,1000 1000,4935 4935,4935 3430,3430 3430,2510 2510,2510 2510,3430 3430,3430

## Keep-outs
Keep-Out Layer:
  the board outline again, w10

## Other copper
Top Layer:
  text "V1.0" at 3025,2064.91 h100
  text "夏宇彬" at 2981.62,1965 h100

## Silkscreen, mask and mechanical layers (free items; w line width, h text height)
Top Overlay:
  text "UART7_TX" at 4420,4320 h40 r90
  text "UART7_RX" at 4665,4320 h40 r90
  text "+" at 1060,4165 h60
  text "+" at 1945,4095 h60
  text "RXTX" at 3020,3975 h60
  text "RXTX" at 3770,3975 h60
  text "12  IN15 14" at 2460.07,3895 h32 r90
  text "123 IN13 12" at 2515.06,3895 h32 r90
  text "123 IN11 10" at 2570.05,3895 h32 r90
  text "3  IN15 14" at 2625.04,3895 h32 r90
  text "3  IN9 8" at 2680.03,3895 h32 r90
  text "3  IN7 6" at 2735.02,3895 h32 r90
  text "3  IN5 4" at 2790.01,3895 h32 r90
  text "5V GND" at 2845,3895 h32 r90
  text "GND" at 4624.97,3705 h50
  text "图书馆自主还书系统" at 1990,3610 h300
  text "RST" at 4624.97,3603.75 h50
  text "SWCLK" at 4525,3502.5 h50
  text "SWDIO" at 4533.33,3401.25 h50
  text "5V" at 4674.95,3300 h50
  text "CAN1_L" at 4580,3005 h40 r90
  text "CAN1_H" at 4925,3005 h40 r90
  text "RXTX" at 1700,2875 h60 r90
  text "BOOT1" at 1995,2460 h60
  text "BOOT0" at 1995,2360 h60
  text "CAN2_H" at 4450,2250 h40
  text "RST" at 2155,2200 h60
  text "CAN2_L" at 4450,2160 h40
  text "+" at 1905,1810 h60
  text "ADC123" at 2648.14,1710 h32 r90
  text "GND GND" at 2701.26,1710 h32 r90
  text "3V3 5V" at 2754.38,1710 h32 r90
  text "IN0 IN1" at 2807.51,1710 h32 r90
  text "IN2 IN3" at 2860.63,1710 h32 r90
  text "OUT1 OUT2" at 2913.75,1710 h32 r90
  text "IN6 IN7" at 2966.88,1710 h32 r90
  text "IN8 IN9" at 3020,1710 h32 r90
  text "TIM1_CH1-4 TIM4_CH1-4" at 3425,1700 h32
  text "RX TX CK" at 4760,1655 h40 r90
  text "USART1_TX" at 4340,1455 h40
  text "USART1_RX" at 4340,1055 h40
  text "+" at 1075,1045 h60
Bottom Overlay:
  lines w10: 2605.35,2614.57 2605.35,2604.57 ; 2615,3335 2605,3335 ; 2950,2970 2990,2970 ; 2970,2950 2970,2990 ; 3325,2605 3335,2605 3335,2615 ; 3325,3335 3335,3335 3335,3325 ; 2605,3335 2605,3325 2605,3335 ; 2605.35,2604.57 2615.35,2604.57 2605.35,2604.57
Top Solder:
  text "2019/6/27" at 2918.67,2149.73 h100
Bottom Solder:
  rectangle: 1000,4525 1410,4935
  rectangle: 1015,1595 1415,2000
  lines w190: 1125,2320 1125,3660 ; 1470,2350 1325,2495 1325,3395 1475,3545 1475,3630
